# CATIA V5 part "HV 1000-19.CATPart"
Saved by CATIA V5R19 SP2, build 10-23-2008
Part number: HV 1000-19
Bounding box of the stored display mesh (mm): x -24.865 to 24.865, y -24.997 to 24.997, z 0 to 95
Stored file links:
  C:\Users\Bora\Desktop\3D KATI MODEL- CATIA PART\HV serisi\HV 1000\HV 1000-19.CATPart
  C:\Program Files\Dassault Systemes\B19\intel_a\reffiles\standard\MetricThickPitch.txt
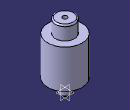
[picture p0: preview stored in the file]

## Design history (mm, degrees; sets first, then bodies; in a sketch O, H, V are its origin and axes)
Body1 (main body)
  Sketch1 on yz-plane, origin (0, 0, 0), H (0, 1, 0), V (0, 0, 1)
    point P1 (14, 93)
    point P3 (14, 93)
    point P8 (8, 17)
    point P10 (8, 1)
    point P11 (8, 17)
    point P12 (8, 1)
    arc A1 centre (12, 93) radius 2 from (14, 93) to (12, 95) ccw
    line L1 (14, 93) -> (14, 75)
    arc A2 centre (8, 18) radius 1 from (8, 19) to (8, 17) ccw
    line L2 (7, 0) -> (8, 1)
    line L3 (8, 17) -> (8, 1)
    line L4 (0, 0) -> (7, 0)
    line L5 (8, 19) -> (25, 19)
    line L6 (14, 75) -> (25, 75)
    line L7 (12, 95) -> (0, 95)
    point P13 (0, 95)
    line L8 (25, 75) -> (25, 19)
    horizontal: L4 H, L5 H, L6 H
    coincidence: P13 V, P1 P3, P8 P11, P10 P12
    tangency: L7 A1
    vertical: L8 V
  Shaft1: profile Sketch1, axis Sketch1.V, angle 360
  Sketch2 on face of Shaft1 from Sketch1.L4, origin (0, 0, 0), H (1, 0, 0), V (0, -1, 0)
    point P1 (0, 0)
  Hole1: placed by Sketch2, at (0, 0, 0) direction (0, 0, 1), diameter 13.835, depth 19, threaded "M16", thread diameter 16, thread depth 19, pitch 2
  Sketch3 on face of Shaft1 from Sketch1.L7, origin (0, 0, 95), H (1, 0, 0), V (0, 1, 0)
    point P1 (0, 0)
  Hole2: placed by Sketch3, at (0, 0, 95) direction (0, 0, -1), diameter 6.647, depth 15, threaded "M8", thread diameter 8, thread depth 15, pitch 1.25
